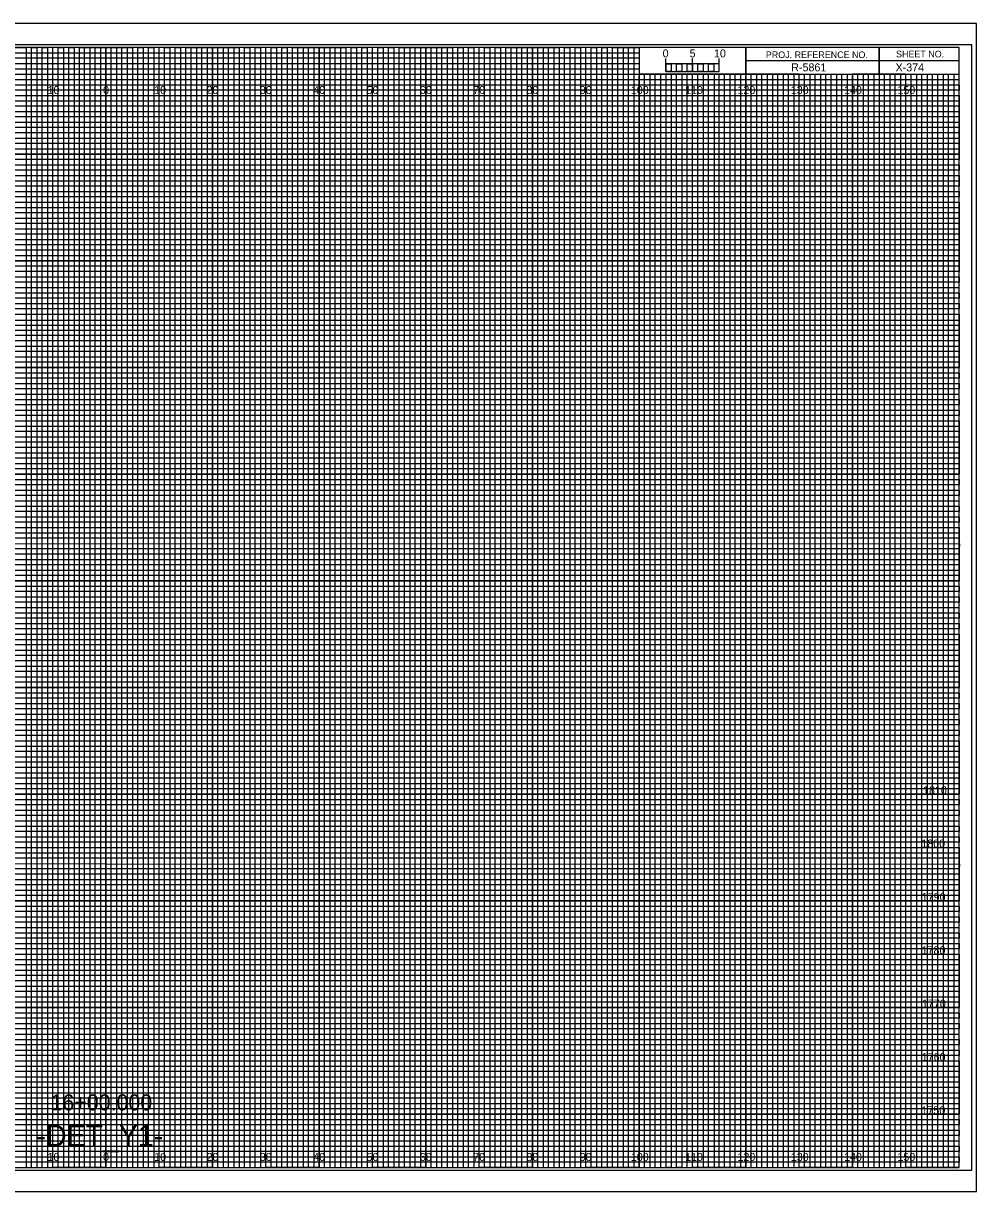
# Model space of a CAD drawing. Extents: x -13 to 323, y -5 to 874.
# Drawn here: x 144.5 to 323.3, y 655.5 to 874.5 of the extents above; entities that cross this region are included whole.
import ezdxf

# ---------------------------------------------------------------- set-up
doc = ezdxf.new("R2010")
doc.units = 0
for name, color, linetype in [('Prop Horizontal Alignment', 7, 'Continuous'), ('Prop XS Alignment Label', 7, 'Continuous'), ('Prop XS Bar Scale Labels', 7, 'Continuous'), ('Prop XS Earthwork Shape', 7, 'Continuous'), ('Prop XS Project Number', 7, 'Continuous'), ('Prop XS Sheet Number', 7, 'Continuous'), ('Raster_Level_0', 7, 'Continuous'), ('Scratch_Level_1', 7, 'Continuous'), ('Scratch_Level_3', 7, 'Continuous'), ('Sheet Cross Section CELL', 7, 'Continuous'), ('Sheet Cross Section Grid Minor 1 CELL', 7, 'Continuous'), ('Sheet Cross Section Grid Minor 2 CELL', 7, 'Continuous'), ('Sheet Cross Section Scale CELL', 7, 'Continuous'), ('Sheet Cutting Line CELL', 7, 'Continuous'), ('Sheet DOT Grid CELL', 7, 'Continuous'), ('Sheet Plot Border Inside CELL', 7, 'Continuous'), ('Sheet Plot Border Outside CELL', 7, 'Continuous')]:
    doc.layers.add(name, color=color, linetype=linetype)

msp = doc.modelspace()

# ---------------------------------------------------------------- linework, layer by layer
at = {"layer": 'Prop XS Earthwork Shape'}
for points in [[(135, 870), (145, 870), (145, 660), (155, 660), (155, 870), (165, 870), (165, 660), (175, 660), (175, 870), (185, 870), (185, 660), (195, 660), (195, 870), (205, 870), (205, 660), (215, 660), (215, 870), (225, 870), (225, 660), (235, 660), (235, 870), (245, 870), (245, 660), (255, 660), (255, 870), (259.93, 870), (260, 870), (260, 865), (264.99, 865), (264.99, 660), (275, 660), (275, 865), (285, 865), (285, 660), (295, 660), (295, 865), (305, 865), (305, 660), (315, 660), (315, 865)], [(0, 865), (275, 865)], [(0, 845), (320, 845), (320, 855), (0, 855)], [(0, 825), (320, 825), (320, 835), (0, 835)], [(0, 805), (320, 805), (320, 815), (0, 815)], [(0, 785), (320, 785), (320, 795), (0, 795)], [(0, 765), (320, 765), (320, 775), (0, 775)], [(0, 745), (320, 745), (320, 755), (0, 755)], [(0, 725), (320, 725), (320, 735), (0, 735)], [(0, 705), (320, 705), (320, 715), (0, 715)], [(0, 685), (320, 685), (320, 695), (0, 695)], [(0, 665), (320, 665), (320, 675), (0, 675)]]:
    msp.add_lwpolyline(points, dxfattribs=at)
at = {"layer": 'Scratch_Level_1'}
for p, q in [((150, 870), (140, 870)), ((150, 660), (150, 870)), ((170, 870), (160, 870)), ((160, 870), (160, 660)), ((170, 660), (170, 870)), ((190, 870), (180, 870)), ((180, 870), (180, 660)), ((190, 660), (190, 870)), ((210, 870), (200, 870)), ((200, 870), (200, 660)), ((210, 660), (210, 870)), ((230, 870), (220, 870)), ((220, 870), (220, 660)), ((230, 660), (230, 870)), ((250, 870), (240, 870)), ((240, 870), (240, 660)), ((250, 660), (250, 870)), ((260, 870), (260, 660)), ((270, 660), (270, 865)), ((290, 865), (280, 865)), ((280, 865), (280, 660)), ((290, 660), (290, 865)), ((310, 865), (300, 865)), ((300, 865), (300, 660)), ((310, 660), (310, 865)), ((160, 660), (150, 660)), ((180, 660), (170, 660)), ((200, 660), (190, 660)), ((220, 660), (210, 660)), ((240, 660), (230, 660)), ((260, 660), (250, 660)), ((280, 660), (270, 660)), ((300, 660), (290, 660)), ((320, 660), (310, 660)), ((320, 660), (320, 660))]:
    msp.add_line(p, q, dxfattribs=at)
for points in [[(0, 860), (320, 860), (320, 850), (0, 850)], [(0, 840), (320, 840), (320, 830), (0, 830)], [(0, 820), (320, 820), (320, 810), (0, 810)], [(0, 800), (320, 800), (320, 790), (0, 790)], [(0, 780), (320, 780), (320, 770), (0, 770)], [(0, 760), (320, 760), (320, 750), (0, 750)], [(0, 740), (320, 740), (320, 730), (0, 730)], [(0, 720), (320, 720), (320, 710), (0, 710)], [(0, 700), (320, 700), (320, 690), (0, 690)], [(0, 680), (320, 680), (320, 670), (0, 670)]]:
    msp.add_lwpolyline(points, dxfattribs=at)
at = {"layer": 'Sheet Cross Section CELL'}
for p, q in [((305, 870), (305, 865)), ((305, 865), (305, 870)), ((280, 867.5), (280, 865)), ((320, 867.49), (280, 867.49)), ((280, 865), (320, 865))]:
    msp.add_line(p, q, dxfattribs=at)
for points in [[(320, 870), (0, 870), (0, 660), (320, 660)], [(280, 870), (260, 870), (260, 865.03), (280, 865.03)], [(320, 870), (280, 870), (280, 865), (320, 865)]]:
    msp.add_lwpolyline(points, close=True, dxfattribs=at)
at = {"layer": 'Sheet Cross Section Grid Minor 1 CELL'}
for p, q in [((0, 869), (260, 869)), ((260, 867.98), (0, 867.98)), ((260, 869), (260, 867.98)), ((0, 867), (260, 867)), ((260, 865.89), (0, 865.89)), ((260, 867), (260, 865.89)), ((0, 864), (320, 864))]:
    msp.add_line(p, q, dxfattribs=at)
for points in [[(0, 863), (270, 863), (320, 863), (320, 862), (0, 862)], [(0, 861), (320, 861), (320, 859), (0, 859)], [(0, 858), (320, 858), (320, 857), (0, 856.98)], [(0, 856), (320, 856), (320, 854), (0, 854)], [(0, 853), (320, 853), (320, 852), (0, 852)], [(0, 851), (320, 851), (320, 849), (0, 849)], [(0, 848), (320, 848), (320, 847), (0, 847)], [(0, 846), (320, 846), (320, 844), (0, 844)], [(0, 843), (320, 843), (320, 842), (0, 842)], [(0, 841), (320, 841), (320, 839), (0, 839)], [(0, 838), (320, 838), (320, 837), (0, 837)], [(0, 836), (320, 836), (320, 833.95), (320, 833), (320, 832), (0, 832)], [(0, 834), (320, 834), (320, 833), (0, 833)], [(0, 831), (320, 831), (320, 829), (0, 829.03)], [(0, 829.03), (320, 829), (320, 828), (0, 828)], [(0, 827), (320, 827), (320, 826), (0, 826)], [(0, 824), (320, 824), (320, 823), (0, 823)], [(0, 822), (320, 822), (320, 821), (0, 821)], [(-0.07, 818.89), (320, 818.89), (320, 817.88), (-0.07, 817.88)], [(0, 817), (320, 817), (320, 816), (0, 816)], [(0, 814), (320, 814), (320, 813), (0, 813)], [(0, 812), (320, 812), (320, 811), (0, 811)], [(0, 809), (320, 809), (320, 808), (0, 808)], [(0, 807), (320, 807), (320, 806), (0, 806)], [(0, 804), (320, 804), (320, 803), (0, 803)], [(0, 802), (320, 802), (320, 801), (0, 801)], [(0, 799), (320, 799), (319.99, 797.98), (0, 798)], [(0, 797), (320, 797), (320, 796), (0, 796)], [(0, 794), (320, 794), (320, 793), (0, 793)], [(0, 792), (320, 792), (320, 791), (0, 791)], [(0, 789), (320, 789), (320, 788), (0, 788)], [(0, 787), (320, 787), (320, 786), (0, 786)], [(0, 784), (320, 784), (320, 783), (0, 783)], [(0, 782), (320, 782), (320, 781), (0, 781)], [(0, 779), (320, 779), (320, 778), (0, 778)], [(0, 776.99), (320.07, 776.91), (320, 776), (0, 776)], [(0, 774), (320, 774), (320, 773), (0, 773)], [(0, 772), (320, 772), (320, 771), (0, 771)], [(0, 769), (320, 769), (320, 768), (0, 768)], [(0, 767), (320, 767), (320, 766), (0, 766)], [(0, 764), (320, 764), (320, 763), (0, 763)], [(0, 762), (320, 762), (320, 761), (0, 761)], [(0, 759), (320, 759), (320, 758), (0, 758)], [(0, 757), (320, 757), (320, 756), (0, 756)], [(0, 754), (320, 754), (320, 753), (0, 753)], [(0, 752), (320, 752), (320, 751), (0, 751)], [(0, 749), (320, 749), (320, 748), (0, 748)], [(0, 747), (320, 747), (320, 746), (0, 746)], [(0, 744), (320, 744), (320, 743), (0, 743)], [(0, 742), (320, 742), (320, 741), (0, 741)], [(0, 739), (320, 739), (319.99, 737.98), (0, 738)], [(0, 737), (320, 737), (320, 736), (0, 736)], [(0, 734), (320, 734), (320, 733), (0, 733)], [(0, 732), (320, 732), (320, 731), (0, 731)], [(0, 729), (320, 729), (320, 728), (0, 728)], [(0, 727), (320, 727), (320, 726), (0, 726)], [(0, 724), (320, 724), (320, 723), (0, 723)], [(0, 722), (320, 722), (320, 721), (0, 721)], [(0, 719), (320, 719), (320, 718), (0, 718)], [(0, 716.99), (320.07, 716.91), (320, 716), (0, 716)], [(0, 714), (320, 714), (320, 713), (0, 713)], [(0, 712), (320, 712), (320, 711), (0, 711)], [(0, 709), (320, 709), (320, 708), (0, 708)], [(0, 707), (320, 707), (320, 706), (0, 706)], [(0, 704), (320, 704), (320, 703), (0, 703)], [(0, 702), (320, 702), (320, 701), (0, 701)], [(0, 699), (320, 699), (320, 698), (0, 698)], [(0, 697), (320, 697), (320, 696), (0, 696)], [(0, 694), (320, 694), (320, 693), (0, 693)], [(0, 692), (320, 692), (320, 691), (0, 691)], [(0, 689), (320, 689), (320, 688), (0, 688)], [(0, 687), (320, 687), (320, 686), (0, 686)], [(0, 684), (320, 684), (320, 683), (0, 683)], [(0, 682), (320, 682), (320, 681), (0, 681)], [(0, 679), (320, 679), (320, 678), (0, 678)], [(0, 677), (320, 677), (320, 676), (0, 676)], [(0, 674), (320, 674), (320, 673), (0, 673)], [(0, 672), (320, 672), (320, 671), (0, 671)], [(0, 669), (320, 669), (320, 668), (0, 668)], [(0, 667), (320, 667), (320, 666), (0, 666)], [(0, 664), (320, 664), (320, 663), (0, 663)], [(0, 662), (320, 662), (320, 661), (0, 661)]]:
    msp.add_lwpolyline(points, dxfattribs=at)
at = {"layer": 'Sheet Cross Section Grid Minor 2 CELL'}
for p, q in [((267, 865), (266.01, 865)), ((266.01, 865), (266.01, 660)), ((267, 660), (267, 865)), ((269, 865), (268, 865)), ((268, 865), (268, 660)), ((269, 660), (269, 865)), ((266.01, 660), (265, 660)), ((268, 660), (267, 660))]:
    msp.add_line(p, q, dxfattribs=at)
for points in [[(145, 660), (146, 660), (146, 870), (147, 870), (147, 660)], [(147, 660), (148, 660), (148, 870), (149, 870), (149, 660)], [(150, 660), (151, 660), (151, 870), (152, 870), (152, 660)], [(152, 660), (153, 660), (153, 870), (154, 870), (154, 660)], [(155, 660), (156, 660), (156, 870), (157, 870), (157, 660)], [(157, 660), (158, 660), (158, 870), (159, 870), (159, 660)], [(160, 660), (161, 660), (161, 870), (162, 870), (162, 660)], [(162, 660), (163, 660), (163, 870), (164, 870), (164, 660)], [(165, 660), (166, 660), (166, 870), (167, 870), (167, 660)], [(167, 660), (168, 660), (168, 870), (169, 870), (169, 660)], [(170, 660), (171, 660), (171, 870), (172, 870), (172, 660)], [(172, 660), (173, 660), (173, 870), (174, 870), (174, 660)], [(175, 660), (176, 660), (176, 870), (177, 870), (177, 660)], [(177, 660), (178, 660), (178, 870), (179, 870), (179, 660)], [(180, 660), (181, 660), (181, 870), (182, 870), (182, 660)], [(182, 660), (183, 660), (183, 870), (184, 870), (184, 660)], [(185, 660), (186, 660), (186, 870), (187, 870), (187, 660)], [(187, 660), (188, 660), (188, 870), (189, 870), (189, 660)], [(190, 660), (191, 660), (191, 870), (192, 870), (192, 660)], [(192, 660), (193, 660), (193, 870), (194, 870), (194, 660)], [(195, 660), (196, 660), (196, 870), (197, 870), (197, 660)], [(197, 660), (198, 660), (198, 870), (199, 870), (199, 660)], [(200, 660), (201, 660), (201, 870), (202, 870), (202, 660)], [(202, 660), (203, 660), (203, 870), (204, 870), (204, 660)], [(205, 660), (206, 660), (206, 870), (207, 870), (207, 660)], [(207, 660), (208, 660), (208, 870), (209, 870), (209, 660)], [(210, 660), (211, 660), (211, 870), (212, 870), (212, 660)], [(212, 660), (213, 660), (213, 870), (214, 870), (214, 660)], [(215, 660), (216, 660), (216, 870), (217, 870), (217, 660)], [(217, 660), (218, 660), (218, 870), (219, 870), (219, 660)], [(220, 660), (221, 660), (221, 870), (222, 870), (222, 660)], [(222, 660), (223, 660), (223, 870), (224, 870), (224, 660)], [(225, 660), (226, 660), (226, 870), (227, 870), (227, 660)], [(227, 660), (228, 660), (228, 870), (229, 870), (229, 660)], [(230, 660), (231, 660), (231, 870), (232, 870), (232, 660)], [(232, 660), (233, 660), (233, 870), (234, 870), (234, 660)], [(235, 660), (236, 660), (236, 870), (237, 870), (237, 660)], [(237, 660), (238, 660), (238, 870), (239, 870), (239, 660)], [(240, 660), (241, 660), (241, 870), (242, 870), (242, 660)], [(242, 660), (243, 660), (243, 870), (244, 870), (244, 660)], [(245, 660), (246, 660), (246, 870), (247, 870), (247, 660)], [(247, 660), (248, 660), (248, 870), (249, 870), (249, 660)], [(250, 660), (251, 660), (251, 870), (252, 870), (252, 660)], [(252, 660), (253, 660), (253, 870), (254, 870), (254, 660)], [(255, 660), (256, 660), (256, 870), (257, 870), (257, 660)], [(257, 660), (258, 660), (258, 870), (259, 870), (259, 660)], [(260, 660), (261, 660), (261, 865), (262.02, 865), (262.02, 660)], [(262, 660), (263, 660), (263, 865), (263.99, 865), (263.99, 660)], [(270, 660), (270.98, 660), (270.98, 865), (272, 865), (272, 660)], [(272, 660), (273, 660), (273, 865), (274.05, 865), (274.05, 660)], [(275, 660), (276, 660), (276, 865), (277, 865), (277, 660)], [(277, 660), (278, 660), (278, 865), (279, 865), (279, 660)], [(280, 660), (281, 660), (281, 865), (282, 865), (282, 660)], [(282, 660), (283, 660), (283, 865), (284, 865), (284, 660)], [(285, 660), (286, 660), (286, 865), (287, 865), (287, 660)], [(287, 660), (288, 660), (288, 865), (289, 865), (289, 660)], [(290, 660), (291, 660), (291, 865), (292, 865), (292, 660)], [(292, 660), (293, 660), (293, 865), (294, 865), (294, 660)], [(295, 660), (296, 660), (296, 865), (297, 865), (297, 660)], [(297, 660), (298, 660), (298, 865), (299, 865), (299, 660)], [(300, 660), (301, 660), (301, 865), (302, 865), (302, 660)], [(302, 660), (303, 660), (303, 865), (304, 865), (304, 660)], [(305, 660), (306, 660), (306, 865), (307, 865), (307, 660)], [(307, 660), (308, 660), (308, 865), (309, 865), (309, 660)], [(310, 660), (311, 660), (311, 865), (312, 865), (312, 660)], [(312, 660), (313, 660), (313, 865), (314, 865), (314, 660)], [(315, 660), (316, 660), (316, 865), (317, 865), (317, 660)], [(317, 660), (318, 660), (318, 865), (319, 865), (319, 660)]]:
    msp.add_lwpolyline(points, dxfattribs=at)
at = {"layer": 'Sheet Cross Section Scale CELL'}
for p, q in [((265, 865.49), (265, 867.9)), ((265, 866.9), (265, 867.9)), ((270, 865.49), (270, 867.9)), ((275, 865.49), (275, 867.9)), ((275, 866.9), (275, 867.9))]:
    msp.add_line(p, q, dxfattribs=at)
for points in [[(275, 866.9), (265, 866.9), (265, 865.49), (275, 865.49)], [(265, 866.9), (266, 866.9), (266, 865.49), (265, 865.49)], [(267, 866.9), (268, 866.9), (268, 865.49), (267, 865.49)], [(269, 866.9), (270, 866.9), (270, 865.49), (269, 865.49)], [(271, 866.9), (272, 866.9), (272, 865.49), (271, 865.49)], [(273, 866.9), (274, 866.9), (274, 865.49), (273, 865.49)]]:
    msp.add_lwpolyline(points, close=True, dxfattribs=at)
at = {"layer": 'Sheet Cutting Line CELL'}
for p, q in [((323.3, 874.5), (-13.4, 874.5)), ((-13.4, 655.5), (323.3, 655.5))]:
    msp.add_line(p, q, dxfattribs=at)
at = {"layer": 'Sheet DOT Grid CELL'}
for p, q in [((150, 660), (150, 870)), ((160, 660), (160, 870)), ((170, 660), (170, 870)), ((180, 660), (180, 870)), ((190, 660), (190, 870)), ((200, 660), (200, 870)), ((210, 660), (210, 870)), ((220, 660), (220, 870)), ((230, 660), (230, 870)), ((240, 660), (240, 870)), ((250, 660), (250, 870)), ((260, 660), (260, 864.69)), ((270, 660), (270, 864.69)), ((280, 660), (280, 864.69)), ((290, 660), (290, 864.69)), ((300, 660), (300, 864.69)), ((310, 660), (310, 864.69)), ((0, 860), (320, 860)), ((0, 850), (320, 850)), ((0, 840), (320, 840)), ((0, 830), (320, 830)), ((0, 820), (320, 820)), ((0, 810), (320, 810)), ((0, 800), (320, 800)), ((0, 790), (320, 790)), ((0, 780), (320, 780)), ((0, 770), (320, 770)), ((0, 760), (320, 760)), ((0, 750), (320, 750)), ((0, 740), (320, 740)), ((0, 730), (320, 730)), ((0, 720), (320, 720)), ((0, 710), (320, 710)), ((0, 700), (320, 700)), ((0, 690), (320, 690)), ((0, 680), (320, 680)), ((0, 670), (320, 670))]:
    msp.add_line(p, q, dxfattribs=at)
at = {"layer": 'Sheet Plot Border Inside CELL'}
msp.add_lwpolyline([(-10.8, 659.5), (322.4, 659.5), (322.4, 870.5), (-10.8, 870.5)], close=True, dxfattribs=at)
at = {"layer": 'Sheet Plot Border Outside CELL'}
msp.add_lwpolyline([(-13.4, 655.5), (323.3, 655.5), (323.3, 874.5), (-13.4, 874.5)], close=True, dxfattribs=at)

# ---------------------------------------------------------------- texts
at = {"layer": 'Prop Horizontal Alignment'}
msp.add_text('16+00.000', height=3, dxfattribs=at).set_placement((149.59, 670.73))
at = {"layer": 'Prop XS Alignment Label'}
msp.add_text('-DET_Y1-', height=4, dxfattribs=at).set_placement((146.97, 664))
at = {"layer": 'Prop XS Bar Scale Labels'}
for s, p in [('5', (269.47, 868.12)), ('10', (274.04, 868.12))]:
    msp.add_text(s, height=1.5, dxfattribs=at).set_placement(p)
at = {"layer": 'Prop XS Project Number'}
msp.add_text('R-5861', height=1.5, dxfattribs=at).set_placement((288.53, 865.5))
at = {"layer": 'Prop XS Sheet Number'}
msp.add_text('X-374', height=1.5, dxfattribs=at).set_placement((308.09, 865.5))
at = {"layer": 'Raster_Level_0'}
for s, p in [('10', (149.04, 861.25)), ('0', (159.45, 861.25)), ('0', (159.45, 861.25)), ('10', (169.04, 861.25)), ('20', (178.86, 861.25)), ('30', (188.86, 861.25)), ('40', (198.86, 861.25)), ('50', (208.86, 861.25)), ('60', (218.86, 861.25)), ('70', (228.86, 861.25)), ('80', (238.86, 861.25)), ('90', (248.86, 861.25)), ('100', (258.44, 861.25)), ('110', (268.62, 861.25)), ('120', (278.44, 861.25)), ('130', (288.44, 861.25)), ('140', (298.44, 861.25)), ('150', (308.44, 861.25)), ('10', (149.04, 661.25)), ('0', (159.45, 661.25)), ('0', (159.45, 661.25)), ('10', (169.04, 661.25)), ('20', (178.86, 661.25)), ('30', (188.86, 661.25)), ('40', (198.86, 661.25)), ('50', (208.86, 661.25)), ('60', (218.86, 661.25)), ('70', (228.86, 661.25)), ('80', (238.86, 661.25)), ('90', (248.86, 661.25)), ('100', (258.44, 661.25)), ('110', (268.62, 661.25)), ('120', (278.44, 661.25)), ('130', (288.44, 661.25)), ('140', (298.44, 661.25)), ('150', (308.44, 661.25))]:
    msp.add_text(s, height=1.5, dxfattribs=at).set_placement(p)
at = {"layer": 'Scratch_Level_3'}
for s, p in [('1810', (313.25, 730)), ('1800', (312.92, 720)), ('1790', (313, 710)), ('1780', (312.98, 700)), ('1770', (313.04, 690)), ('1760', (313, 680)), ('1750', (312.96, 670))]:
    msp.add_text(s, height=1.5, dxfattribs=at).set_placement(p)
at = {"layer": 'Sheet Cross Section CELL'}
for s, p in [('PROJ. REFERENCE NO.', (283.77, 867.99)), ('SHEET NO.', (308.19, 868.12))]:
    msp.add_text(s, height=1.25, dxfattribs=at).set_placement(p)
at = {"layer": 'Sheet Cross Section Scale CELL'}
msp.add_text('0', height=1.5, dxfattribs=at).set_placement((264.41, 868.12))

doc.saveas('drawing.dxf')
